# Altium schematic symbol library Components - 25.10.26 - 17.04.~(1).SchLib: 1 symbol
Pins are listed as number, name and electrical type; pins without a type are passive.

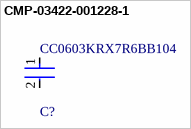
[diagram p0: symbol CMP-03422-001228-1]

## CMP-03422-001228-1
designator C?, comment CC0603KRX7R6BB104
CAP CER 0.1UF 10V X7R 0603; Manufacturer: YAGEO; Material: Ceramic; Tolerance: 0.1; Capacitance: 100 nF; Temperature Coefficient: 15%; Value: 100 nF
footprint FP-CC0603-DA-IPC_B
footprint FP-CC0603-DA-IPC_A
footprint FP-CC0603-DA-IPC_C
footprint FP-CC0603-DA-MFG
pins: 1, 2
